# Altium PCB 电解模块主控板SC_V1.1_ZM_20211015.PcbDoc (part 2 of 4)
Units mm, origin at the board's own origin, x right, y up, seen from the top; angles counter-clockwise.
Board outline 150.25 x 100.26 mm, 2 copper layers (Top Layer, Bottom Layer); 222 components, 167 nets, 677 pads, 2045 vias.
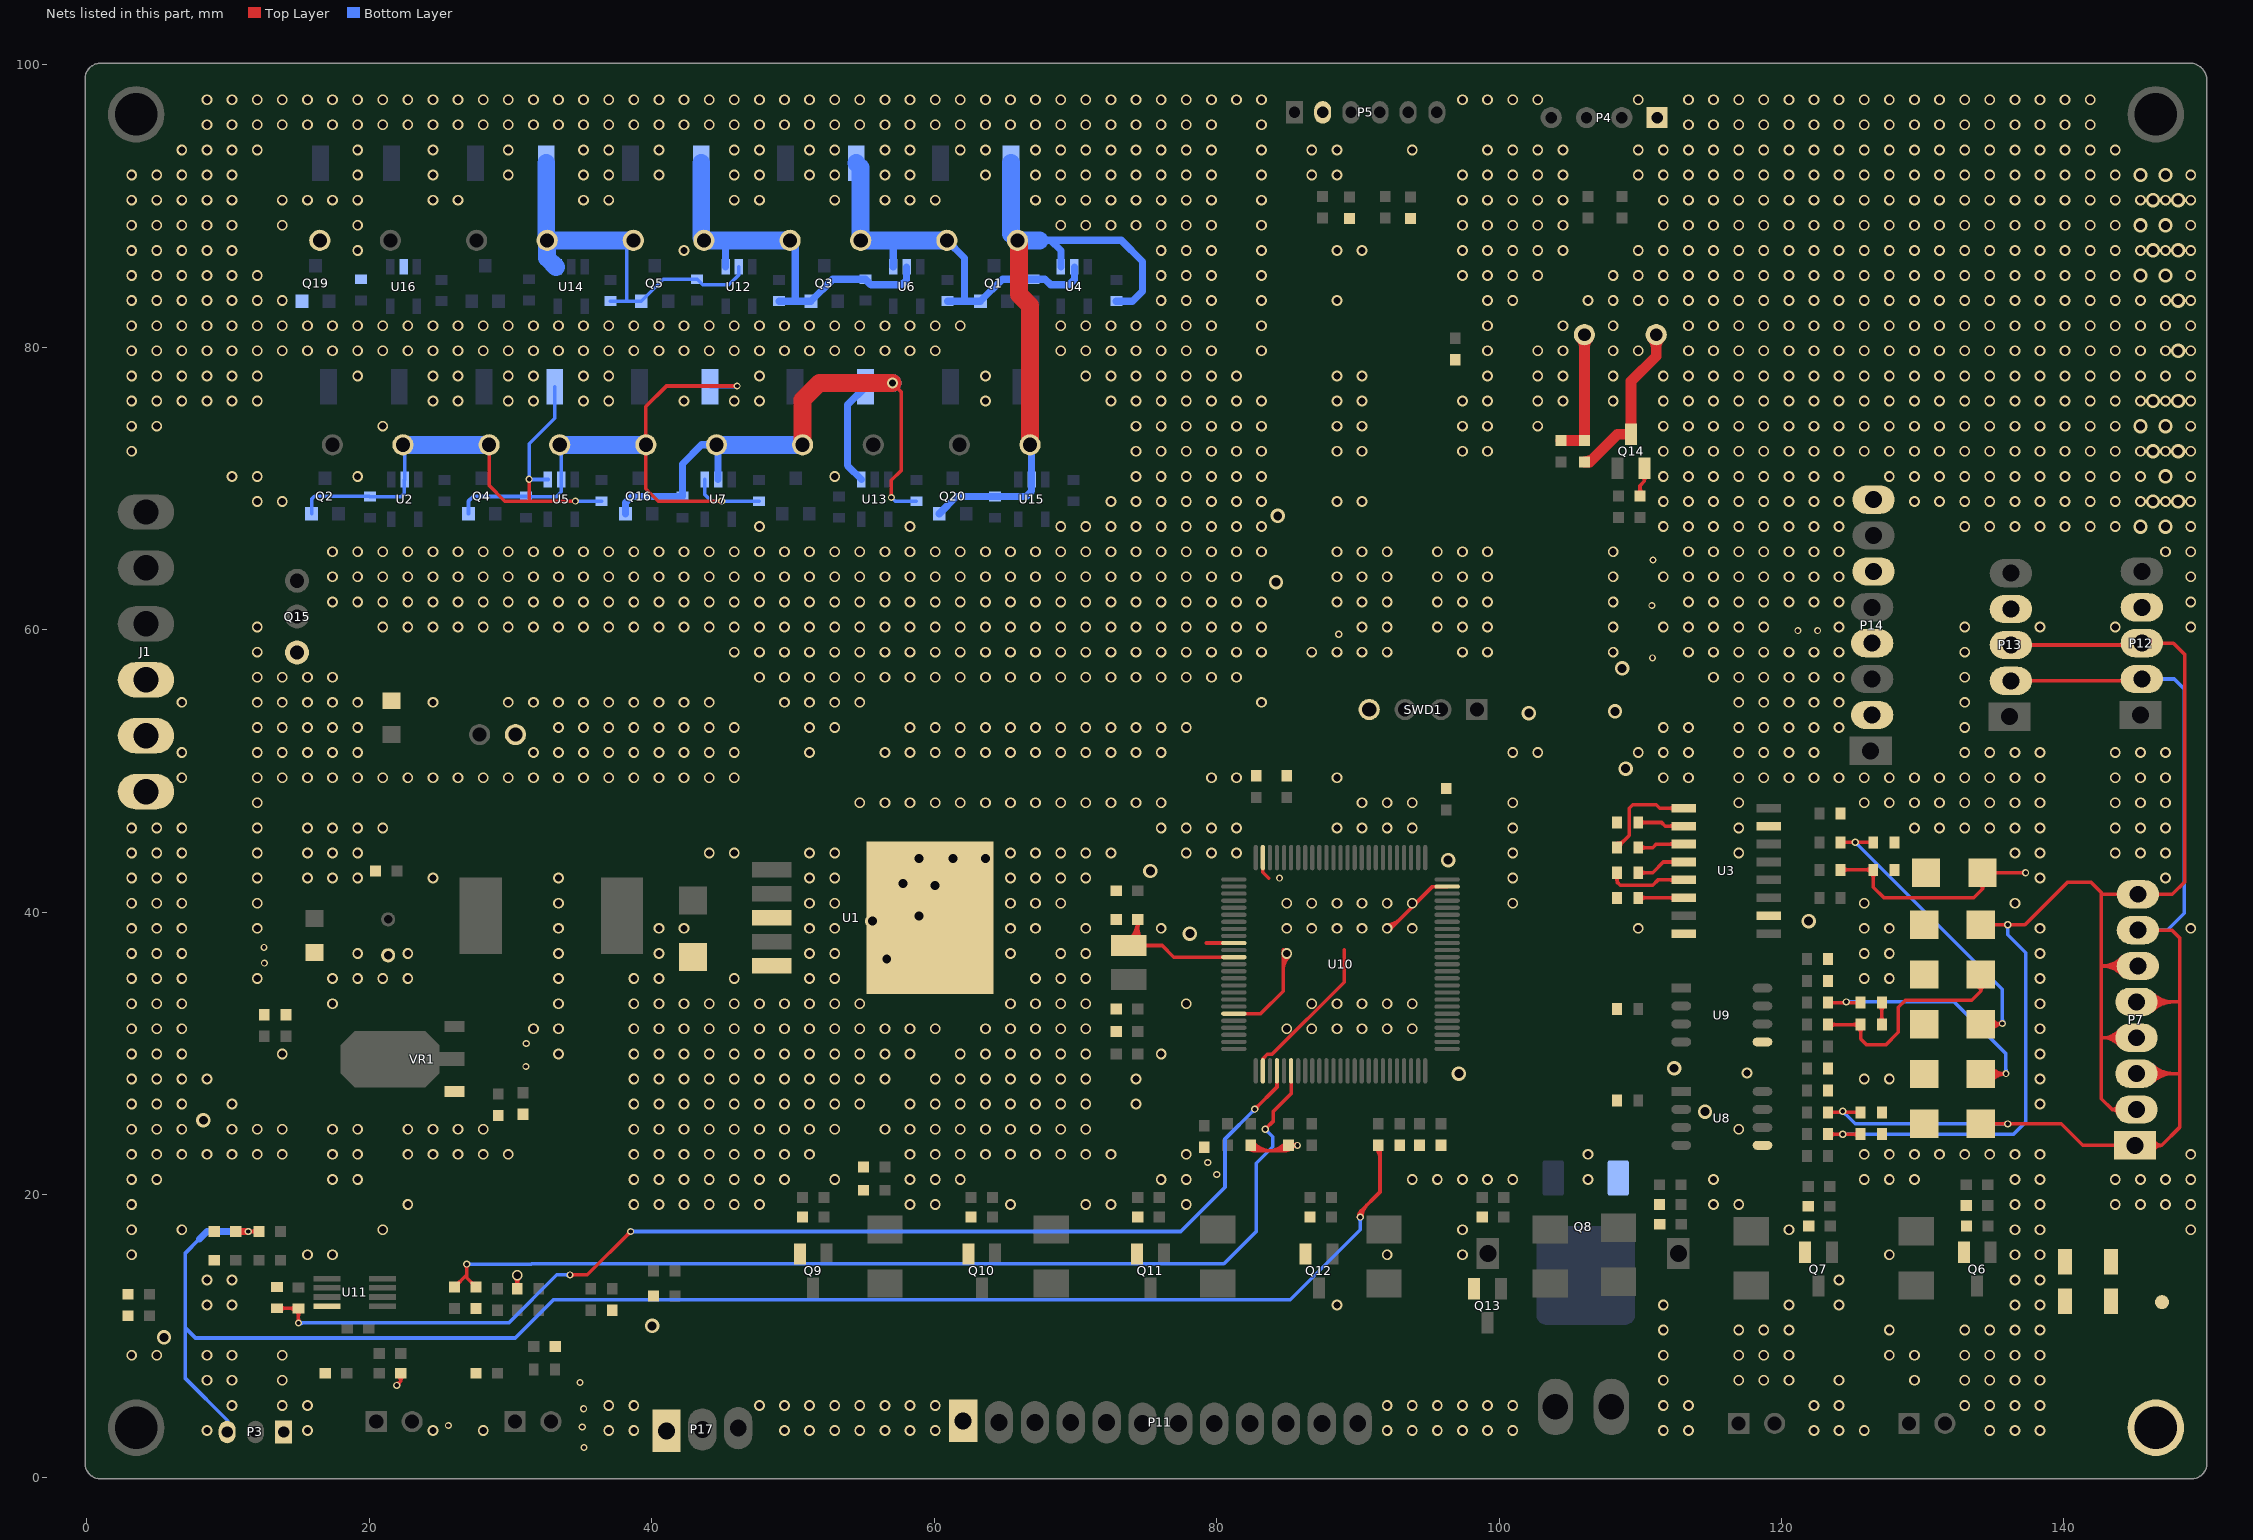
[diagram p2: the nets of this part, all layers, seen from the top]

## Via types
v1: diameter 0.762, hole 0.508, Top Layer to Bottom Layer, tented both sides, 1838 vias
v2: diameter 0.508, hole 0.305, Top Layer to Bottom Layer, tented both sides, 135 vias
v3: diameter 1.016, hole 0.635, Top Layer to Bottom Layer, tented both sides, 63 vias
v4: diameter 2.032, hole 1.524, Top Layer to Bottom Layer, tented both sides, 4 vias
v5: diameter 1.27, hole 0.762, Top Layer to Bottom Layer, tented both sides, 4 vias
v6: diameter 2.54, hole 2.032, Top Layer to Bottom Layer, tented both sides, 1 vias

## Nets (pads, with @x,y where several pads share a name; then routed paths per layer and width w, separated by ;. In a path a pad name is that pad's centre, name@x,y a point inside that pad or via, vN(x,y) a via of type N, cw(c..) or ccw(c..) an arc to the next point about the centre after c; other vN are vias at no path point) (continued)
GND: C1.2 C2.2 C3.1 C4.1 C5.1 C6.1 C8.1 C9.1 C10.1 C12.1 C13.1 C14.1 C15.1 C16.1 C17.1 C22.2 C24.2 C25.2 C27.2 C28.2 C29.2 C30.2 C31.2 C32.1 C33.2 C34.2 C35.2 C36.2 C37.1 C38.1 C39.1 C40.1 C43.2 C45.1 C46.1 C47.1 C50.2 C51.1 C52.1 C55.1 C56.1 C57.1 D3.1 D14.2 D15.2 D16.2 D17.2 D18.2 D19.2 J1.1 J1.2 J1.3 P3.1 P4.1 P5.2 P11.1 P12.4 P13.4 P14.2 P14.4 P14.6 P14.8 P17.1 Q6.2 Q7.2 Q8.2 Q9.2 Q10.2 Q11.2 Q12.2 Q13.2 Q14.2 Q15.1 Q19.2 R22.1 R34.2 R35.2 R36.2 R42.2 R43.2 R44.2 R45.2 R46.2 R59.2 R70.2 R71.2 R72.1 R76.2 R77.2 R79.1 R113.2 SWD1.4 TVS1.1 TVS2.1 TVS3.1 TVS4.1 TVS5.1 TVS6.1 TVS7.1 TVS8.1 TVS9.1 TVS10.1 TVS11.1 TVS12.1 U1.3 U1.5 U1.6 U3.8 U3.10 U3.15 U8.5 U9.5 U10.10 U10.20 U10.27 U10.74 U10.99 U11.4 U16.2 VR1.1 | length 53.5
  Top Layer w0.254: v2(21.946,6.502) 22.225,6.782 ; v2@21.946,6.629 ccw(c21.946,6.936) 22.162,6.719 ccw(c22.379,6.502) v2@22.073,6.502 ; TVS6.1@22.052,7.18 cw(c21.68,6.782) 22.225,6.782 ; TVS6.1@22.225,7.366 22.225,6.782 ; TVS6.1@22.398,7.18 ccw(c22.77,6.782) 22.225,6.782 ; TVS11.1@30.3,13.534 ccw(c29.867,13.967) 30.48,13.967 ccw(c31.093,13.967) TVS11.1@30.66,13.534 ; v1@30.3,14.121 cw(c29.867,13.687) 30.48,13.687 cw(c31.093,13.687) v1@30.66,14.121 ; TVS11.1@30.48,13.335 v1(30.48,14.3) ; 79.272,37.822 U10.10@81.223,37.822 ; U10.20@81.223,32.822 83.114,32.822 84.709,34.417 v1@84.709,37.338 ; C51.1@82.243,23.296 ccw(c82.684,23.737) C51.1@82.684,23.114 ; C51.1@82.423,23.476 ccw(c83.297,24.35) 83.297,23.114 ; C51.1@82.603,23.656 ccw(c83.91,24.963) 83.91,23.114 ; 82.804,23.114 84.709,23.114 C38.1@85.09,23.495 v2(85.725,23.495) ; U10.27@83.273,28.772 83.273,29.629 83.595,29.951 83.926,29.951 89.027,35.052 89.027,37.338 ; U10.99@83.273,43.872 83.273,42.838 83.693,42.418 ; U10.27@83.296,29.522 cw(c83.61,29.522) 83.388,29.744 ; 83.603,23.114 ccw(c83.603,24.963) C38.1@84.91,23.656 ; 84.216,23.114 ccw(c84.216,24.35) C38.1@85.09,23.476 ; 84.709,35.858 cw(c86.189,35.858) v1@85.143,36.904 ; 84.709,36.471 cw(c85.576,36.471) v1(84.963,37.084) ; C38.1@84.829,23.114 ccw(c84.829,23.737) C38.1@85.27,23.296 ; C38.1@85.27,23.315 cw(c85.703,22.882) 85.703,23.495 cw(c85.703,24.108) C38.1@85.27,23.675 ; v2@85.635,23.405 ccw(c85.418,23.188) 85.418,23.495 ccw(c85.418,23.802) v2@85.635,23.585 ; v1(92.075,38.862) ccw(c92.075,39.475) 92.509,39.042 ; v1@92.075,39.116 ccw(c92.075,40.342) 92.942,39.475 ; v1@92.202,38.735 95.289,41.822 U10.74@96.323,41.822 ; R59.2@109.802,69.649 ccw(c109.369,70.082) 109.982,70.082 ccw(c110.595,70.082) R59.2@110.162,69.649 ; R59.2@109.982,69.469 109.982,70.206 110.287,70.51 ; Q14.2@110.108,70.889 cw(c109.797,70.51) 110.287,70.51 ; Q14.2@110.297,71.444 110.287,71.434 110.287,70.51 ; Q14.2@110.473,70.879 ccw(c110.744,70.51) 110.287,70.51 ; C35.2@126.945,32.279 ccw(c126.565,32.66) 127.103,32.66 ccw(c127.641,32.66) C35.2@127.261,32.279 ; C34.2@126.945,33.366 cw(c126.565,32.985) 127.103,32.985 cw(c127.641,32.985) C34.2@127.261,33.366 ; C35.2@127.103,32.046 C34.2@127.103,33.599
  other v1: 8.509,3.302 15.621,3.302 24.511,3.302 28.067,3.302 36.957,3.302 38.735,3.302 49.403,3.302 51.181,3.302 52.959,3.302 54.737,3.302 56.515,3.302 58.293,3.302 60.071,3.302 92.075,3.302 93.853,3.302 95.631,3.302 97.409,3.302 99.187,3.302 100.965,3.302 111.633,3.302 113.411,3.302 122.301,3.302 124.079,3.302 125.857,3.302 134.747,3.302 136.525,3.302 138.303,3.302 10.287,5.08 13.843,5.08 15.621,5.08 36.957,5.08 38.735,5.08 47.625,5.08 49.403,5.08 51.181,5.08 52.959,5.08 54.737,5.08 56.515,5.08 58.293,5.08 60.071,5.08 92.075,5.08 93.853,5.08 95.631,5.08 97.409,5.08 99.187,5.08 100.965,5.08 111.633,5.08 113.411,5.08 122.301,5.08 124.079,5.08 132.969,5.08 134.747,5.08 136.525,5.08 138.303,5.08 8.509,6.858 10.287,6.858 13.843,6.858 111.633,6.858 116.967,6.858 118.745,6.858 120.523,6.858 124.079,6.858 129.413,6.858 132.969,6.858 134.747,6.858 136.525,6.858 138.303,6.858 3.175,8.636 4.953,8.636 8.509,8.636 10.287,8.636 13.843,8.636 111.633,8.636 116.967,8.636 118.745,8.636 120.523,8.636 127.635,8.636 129.413,8.636 132.969,8.636 134.747,8.636 136.525,8.636 138.303,8.636 111.633,10.414 116.967,10.414 118.745,10.414 120.523,10.414 127.635,10.414 132.969,10.414 134.747,10.414 136.525,10.414 138.303,10.414 8.509,12.192 10.287,12.192 88.519,12.192 111.633,12.192 120.523,12.192 124.079,12.192 136.525,12.192 138.303,12.192 8.509,13.97 10.287,13.97 124.079,13.97 136.525,13.97 138.303,13.97 3.175,15.748 15.621,15.748 17.399,15.748 92.075,15.748 97.409,15.748 127.635,15.748 136.525,15.748 138.303,15.748 3.175,17.526 6.731,17.526 20.955,17.526 97.409,17.526 120.523,17.526 136.525,17.526 138.303,17.526 148.971,17.526 3.175,19.304 22.733,19.304 38.735,19.304 40.513,19.304 42.291,19.304 44.069,19.304 45.847,19.304 47.625,19.304 58.293,19.304 60.071,19.304 65.405,19.304 70.739,19.304 72.517,19.304 77.851,19.304 115.189,19.304 116.967,19.304 136.525,19.304 138.303,19.304 143.637,19.304 145.415,19.304 147.193,19.304 148.971,19.304 3.175,21.082 4.953,21.082 17.399,21.082 19.177,21.082 38.735,21.082 40.513,21.082 42.291,21.082 44.069,21.082 45.847,21.082 47.625,21.082 49.403,21.082 52.959,21.082 58.293,21.082 60.071,21.082 61.849,21.082 76.073,21.082 77.851,21.082 93.853,21.082 95.631,21.082 97.409,21.082 99.187,21.082 100.965,21.082 106.299,21.082 115.189,21.082 125.857,21.082 127.635,21.082 129.413,21.082 136.525,21.082 138.303,21.082 143.637,21.082 145.415,21.082 147.193,21.082 148.971,21.082 3.175,22.86 4.953,22.86 6.731,22.86 8.509,22.86 10.287,22.86 12.065,22.86 13.843,22.86 17.399,22.86 19.177,22.86 22.733,22.86 24.511,22.86 26.289,22.86 28.067,22.86 29.845,22.86 38.735,22.86 40.513,22.86 42.291,22.86 44.069,22.86 45.847,22.86 47.625,22.86 49.403,22.86 51.181,22.86 58.293,22.86 60.071,22.86 61.849,22.86 63.627,22.86 65.405,22.86 67.183,22.86 68.961,22.86 70.739,22.86 72.517,22.86 77.851,22.86 106.299,22.86 125.857,22.86 127.635,22.86 129.413,22.86 131.191,22.86 132.969,22.86 134.747,22.86 136.525,22.86 138.303,22.86 148.971,22.86 3.175,24.638 4.953,24.638 6.731,24.638 10.287,24.638 12.065,24.638 13.843,24.638 17.399,24.638 19.177,24.638 22.733,24.638 24.511,24.638 26.289,24.638 28.067,24.638 38.735,24.638 40.513,24.638 42.291,24.638 44.069,24.638 45.847,24.638 47.625,24.638 49.403,24.638 51.181,24.638 52.959,24.638 56.515,24.638 58.293,24.638 60.071,24.638 61.849,24.638 63.627,24.638 65.405,24.638 67.183,24.638 68.961,24.638 70.739,24.638 116.967,24.638 3.175,26.416 4.953,26.416 6.731,26.416 10.287,26.416 38.735,26.416 40.513,26.416 42.291,26.416 44.069,26.416 45.847,26.416 47.625,26.416 49.403,26.416 51.181,26.416 52.959,26.416 54.737,26.416 58.293,26.416 60.071,26.416 61.849,26.416 63.627,26.416 65.405,26.416 67.183,26.416 68.961,26.416 70.739,26.416 74.295,26.416 138.303,26.416 3.175,28.194 4.953,28.194 6.731,28.194 8.509,28.194 38.735,28.194 40.513,28.194 42.291,28.194 44.069,28.194 45.847,28.194 47.625,28.194 49.403,28.194 51.181,28.194 52.959,28.194 54.737,28.194 56.515,28.194 60.071,28.194 61.849,28.194 63.627,28.194 65.405,28.194 67.183,28.194 68.961,28.194 70.739,28.194 74.295,28.194 125.857,28.194 127.635,28.194 138.303,28.194 117.551,28.626 3.175,29.972 4.953,29.972 6.731,29.972 13.843,29.972 33.401,29.972 38.735,29.972 40.513,29.972 42.291,29.972 44.069,29.972 45.847,29.972 47.625,29.972 49.403,29.972 51.181,29.972 52.959,29.972 54.737,29.972 56.515,29.972 58.293,29.972 61.849,29.972 63.627,29.972 65.405,29.972 67.183,29.972 68.961,29.972 70.739,29.972 76.073,29.972 138.303,29.972 3.175,31.75 4.953,31.75 6.731,31.75 31.623,31.75 33.401,31.75 38.735,31.75 40.513,31.75 42.291,31.75 44.069,31.75 45.847,31.75 47.625,31.75 49.403,31.75 51.181,31.75 52.959,31.75 54.737,31.75 56.515,31.75 58.293,31.75 60.071,31.75 63.627,31.75 65.405,31.75 67.183,31.75 68.961,31.75 70.739,31.75 84.963,31.75 86.741,31.75 88.519,31.75 90.297,31.75 92.075,31.75 93.853,31.75 138.303,31.75 3.175,33.528 4.953,33.528 6.731,33.528 17.399,33.528 33.401,33.528 38.735,33.528 40.513,33.528 42.291,33.528 44.069,33.528 45.847,33.528 47.625,33.528 49.403,33.528 51.181,33.528 52.959,33.528 54.737,33.528 65.405,33.528 67.183,33.528 68.961,33.528 70.739,33.528 77.851,33.528 86.741,33.528 88.519,33.528 90.297,33.528 92.075,33.528 93.853,33.528 138.303,33.528 3.175,35.306 4.953,35.306 6.731,35.306 12.065,35.306 17.399,35.306 19.177,35.306 20.955,35.306 22.733,35.306 33.401,35.306 38.735,35.306 40.513,35.306 45.847,35.306 51.181,35.306 52.959,35.306 67.183,35.306 68.961,35.306 70.739,35.306 125.857,35.306 127.635,35.306 138.303,35.306 3.175,37.084 4.953,37.084 6.731,37.084 19.177,37.084 22.733,37.084 33.401,37.084 40.513,37.084 51.181,37.084 52.959,37.084 65.405,37.084 68.961,37.084 70.739,37.084 125.857,37.084 127.635,37.084 138.303,37.084 3.175,38.862 4.953,38.862 6.731,38.862 12.065,38.862 33.401,38.862 40.513,38.862 42.291,38.862 51.181,38.862 52.959,38.862 65.405,38.862 67.183,38.862 70.739,38.862 76.073,38.862 84.963,38.862 86.741,38.862 88.519,38.862 90.297,38.862 93.853,38.862 109.855,38.862 125.857,38.862 127.635,38.862 138.303,38.862 148.971,38.862 3.175,40.64 4.953,40.64 6.731,40.64 12.065,40.64 33.401,40.64 51.181,40.64 52.959,40.64 65.405,40.64 67.183,40.64 68.961,40.64 84.963,40.64 86.741,40.64 88.519,40.64 90.297,40.64 92.075,40.64 93.853,40.64 100.965,40.64 125.857,40.64 136.525,40.64 3.175,42.418 4.953,42.418 6.731,42.418 12.065,42.418 15.621,42.418 17.399,42.418 19.177,42.418 24.511,42.418 33.401,42.418 51.181,42.418 52.959,42.418 65.405,42.418 67.183,42.418 68.961,42.418 70.739,42.418 100.965,42.418 138.303,42.418 147.193,42.418 3.175,44.196 4.953,44.196 6.731,44.196 12.065,44.196 15.621,44.196 17.399,44.196 19.177,44.196 44.069,44.196 45.847,44.196 51.181,44.196 52.959,44.196 65.405,44.196 67.183,44.196 68.961,44.196 70.739,44.196 72.517,44.196 77.851,44.196 79.629,44.196 81.407,44.196 100.965,44.196 116.967,44.196 136.525,44.196 138.303,44.196 143.637,44.196 145.415,44.196 147.193,44.196 3.175,45.974 4.953,45.974 6.731,45.974 12.065,45.974 15.621,45.974 17.399,45.974 19.177,45.974 20.955,45.974 76.073,45.974 77.851,45.974 79.629,45.974 81.407,45.974 88.519,45.974 90.297,45.974 92.075,45.974 93.853,45.974 100.965,45.974 116.967,45.974 129.413,45.974 131.191,45.974 132.969,45.974 134.747,45.974 136.525,45.974 138.303,45.974 143.637,45.974 145.415,45.974 147.193,45.974 12.065,47.752 54.737,47.752 56.515,47.752 58.293,47.752 60.071,47.752 61.849,47.752 63.627,47.752 65.405,47.752 67.183,47.752 68.961,47.752 70.739,47.752 72.517,47.752 74.295,47.752 76.073,47.752 90.297,47.752 92.075,47.752 93.853,47.752 100.965,47.752 116.967,47.752 125.857,47.752 127.635,47.752 129.413,47.752 131.191,47.752 132.969,47.752 134.747,47.752 136.525,47.752 138.303,47.752 143.637,47.752 145.415,47.752 147.193,47.752 6.731,49.53 12.065,49.53 13.843,49.53 15.621,49.53 17.399,49.53 19.177,49.53 20.955,49.53 22.733,49.53 24.511,49.53 26.289,49.53 28.067,49.53 29.845,49.53 31.623,49.53 33.401,49.53 35.179,49.53 36.957,49.53 38.735,49.53 40.513,49.53 42.291,49.53 44.069,49.53 45.847,49.53 79.629,49.53 81.407,49.53 88.519,49.53 111.633,49.53 113.411,49.53 116.967,49.53 118.745,49.53 120.523,49.53 122.301,49.53 124.079,49.53 125.857,49.53 127.635,49.53 129.413,49.53 131.191,49.53 132.969,49.53 134.747,49.53 136.525,49.53 138.303,49.53 143.637,49.53 145.415,49.53 147.193,49.53 6.731,51.308 12.065,51.308 13.843,51.308 15.621,51.308 17.399,51.308 19.177,51.308 31.623,51.308 33.401,51.308 35.179,51.308 36.957,51.308 38.735,51.308 40.513,51.308 42.291,51.308 44.069,51.308 45.847,51.308 51.181,51.308 56.515,51.308 58.293,51.308 60.071,51.308 61.849,51.308 63.627,51.308 65.405,51.308 67.183,51.308 68.961,51.308 70.739,51.308 72.517,51.308 74.295,51.308 76.073,51.308 100.965,51.308 102.743,51.308 109.855,51.308 111.633,51.308 113.411,51.308 116.967,51.308 118.745,51.308 120.523,51.308 122.301,51.308 132.969,51.308 134.747,51.308 136.525,51.308 138.303,51.308 143.637,51.308 145.415,51.308 147.193,51.308 12.065,53.086 13.843,53.086 15.621,53.086 17.399,53.086 19.177,53.086 33.401,53.086 35.179,53.086 36.957,53.086 38.735,53.086 40.513,53.086 42.291,53.086 44.069,53.086 45.847,53.086 51.181,53.086 52.959,53.086 58.293,53.086 60.071,53.086 61.849,53.086 63.627,53.086 65.405,53.086 67.183,53.086 68.961,53.086 70.739,53.086 72.517,53.086 74.295,53.086 76.073,53.086 77.851,53.086 111.633,53.086 113.411,53.086 116.967,53.086 118.745,53.086 120.523,53.086 122.301,53.086 124.079,53.086 132.969,53.086 6.731,54.864 12.065,54.864 13.843,54.864 15.621,54.864 17.399,54.864 19.177,54.864 24.511,54.864 29.845,54.864 31.623,54.864 33.401,54.864 35.179,54.864 36.957,54.864 38.735,54.864 40.513,54.864 42.291,54.864 44.069,54.864 49.403,54.864 51.181,54.864 52.959,54.864 54.737,54.864 83.185,54.864 116.967,54.864 118.745,54.864 120.523,54.864 122.301,54.864 124.079,54.864 132.969,54.864 12.065,56.642 13.843,56.642 15.621,56.642 17.399,56.642 47.625,56.642 49.403,56.642 51.181,56.642 52.959,56.642 54.737,56.642 56.515,56.642 58.293,56.642 60.071,56.642 61.849,56.642 63.627,56.642 65.405,56.642 67.183,56.642 68.961,56.642 70.739,56.642 72.517,56.642 74.295,56.642 76.073,56.642 77.851,56.642 79.629,56.642 81.407,56.642 115.189,56.642 116.967,56.642 118.745,56.642 120.523,56.642 122.301,56.642 124.079,56.642 132.969,56.642 12.065,58.42 45.847,58.42 47.625,58.42 49.403,58.42 51.181,58.42 52.959,58.42 54.737,58.42 56.515,58.42 58.293,58.42 60.071,58.42 61.849,58.42 63.627,58.42 65.405,58.42 67.183,58.42 68.961,58.42 70.739,58.42 72.517,58.42 74.295,58.42 76.073,58.42 77.851,58.42 79.629,58.42 81.407,58.42 83.185,58.42 86.741,58.42 88.519,58.42 90.297,58.42 92.075,58.42 97.409,58.42 99.187,58.42 108.077,58.42 113.411,58.42 115.189,58.42 116.967,58.42 118.745,58.42 120.523,58.42 122.301,58.42 124.079,58.42 132.969,58.42 12.065,60.198 20.955,60.198 22.733,60.198 24.511,60.198 26.289,60.198 28.067,60.198 29.845,60.198 31.623,60.198 33.401,60.198 35.179,60.198 36.957,60.198 38.735,60.198 40.513,60.198 42.291,60.198 44.069,60.198 45.847,60.198 47.625,60.198 49.403,60.198 51.181,60.198 52.959,60.198 54.737,60.198 56.515,60.198 58.293,60.198 60.071,60.198 61.849,60.198 63.627,60.198 65.405,60.198 67.183,60.198 68.961,60.198 70.739,60.198 72.517,60.198 74.295,60.198 76.073,60.198 77.851,60.198 79.629,60.198 81.407,60.198 83.185,60.198 90.297,60.198 92.075,60.198 95.631,60.198 97.409,60.198 99.187,60.198 108.077,60.198 111.633,60.198 113.411,60.198 115.189,60.198 116.967,60.198 118.745,60.198 124.079,60.198 132.969,60.198 138.303,60.198 143.637,60.198 148.971,60.198 17.399,61.976 19.177,61.976 20.955,61.976 22.733,61.976 24.511,61.976 26.289,61.976 28.067,61.976 29.845,61.976 31.623,61.976 33.401,61.976 35.179,61.976 36.957,61.976 38.735,61.976 40.513,61.976 42.291,61.976 44.069,61.976 45.847,61.976 47.625,61.976 49.403,61.976 51.181,61.976 52.959,61.976 54.737,61.976 56.515,61.976 58.293,61.976 60.071,61.976 61.849,61.976 63.627,61.976 65.405,61.976 67.183,61.976 68.961,61.976 70.739,61.976 72.517,61.976 74.295,61.976 76.073,61.976 77.851,61.976 79.629,61.976 81.407,61.976 83.185,61.976 88.519,61.976 90.297,61.976 92.075,61.976 95.631,61.976 97.409,61.976 99.187,61.976 108.077,61.976 113.411,61.976 115.189,61.976 116.967,61.976 118.745,61.976 120.523,61.976 122.301,61.976 124.079,61.976 148.971,61.976 17.399,63.754 19.177,63.754 20.955,63.754 22.733,63.754 24.511,63.754 26.289,63.754 28.067,63.754 29.845,63.754 31.623,63.754 33.401,63.754 35.179,63.754 36.957,63.754 38.735,63.754 40.513,63.754 42.291,63.754 44.069,63.754 45.847,63.754 47.625,63.754 49.403,63.754 51.181,63.754 52.959,63.754 54.737,63.754 56.515,63.754 58.293,63.754 60.071,63.754 61.849,63.754 63.627,63.754 65.405,63.754 67.183,63.754 68.961,63.754 70.739,63.754 72.517,63.754 74.295,63.754 76.073,63.754 77.851,63.754 79.629,63.754 81.407,63.754 88.519,63.754 90.297,63.754 92.075,63.754 95.631,63.754 97.409,63.754 99.187,63.754 108.077,63.754 111.633,63.754 113.411,63.754 115.189,63.754 116.967,63.754 118.745,63.754 120.523,63.754 122.301,63.754 124.079,63.754 148.971,63.754 17.399,65.532 19.177,65.532 20.955,65.532 22.733,65.532 24.511,65.532 26.289,65.532 28.067,65.532 29.845,65.532 31.623,65.532 33.401,65.532 35.179,65.532 36.957,65.532 38.735,65.532 40.513,65.532 42.291,65.532 44.069,65.532 45.847,65.532 47.625,65.532 49.403,65.532 51.181,65.532 52.959,65.532 54.737,65.532 56.515,65.532 58.293,65.532 60.071,65.532 61.849,65.532 63.627,65.532 65.405,65.532 67.183,65.532 68.961,65.532 70.739,65.532 72.517,65.532 74.295,65.532 76.073,65.532 77.851,65.532 79.629,65.532 81.407,65.532 83.185,65.532 88.519,65.532 90.297,65.532 92.075,65.532 95.631,65.532 97.409,65.532 99.187,65.532 108.077,65.532 113.411,65.532 115.189,65.532 116.967,65.532 118.745,65.532 120.523,65.532 122.301,65.532 124.079,65.532 147.193,65.532 148.971,65.532 47.625,67.31 58.293,67.31 68.961,67.31 70.739,67.31 72.517,67.31 74.295,67.31 76.073,67.31 77.851,67.31 79.629,67.31 81.407,67.31 83.185,67.31 111.633,67.31 113.411,67.31 115.189,67.31 116.967,67.31 118.745,67.31 120.523,67.31 122.301,67.31 124.079,67.31 132.969,67.31 134.747,67.31 136.525,67.31 138.303,67.31 140.081,67.31 141.859,67.31 143.637,67.31 148.971,67.31 12.065,69.088 13.843,69.088 72.517,69.088 74.295,69.088 76.073,69.088 77.851,69.088 79.629,69.088 81.407,69.088 83.185,69.088 88.519,69.088 90.297,69.088 111.633,69.088 113.411,69.088 115.189,69.088 116.967,69.088 118.745,69.088 120.523,69.088 122.301,69.088 124.079,69.088 129.413,69.088 131.191,69.088 132.969,69.088 134.747,69.088 136.525,69.088 138.303,69.088 140.081,69.088 141.859,69.088 143.637,69.088 145.415,69.088 147.193,69.088 148.971,69.088 10.287,70.866 12.065,70.866 19.177,70.866 52.959,70.866 74.295,70.866 76.073,70.866 77.851,70.866 79.629,70.866 81.407,70.866 83.185,70.866 111.633,70.866 113.411,70.866 115.189,70.866 116.967,70.866 118.745,70.866 120.523,70.866 122.301,70.866 124.079,70.866 127.635,70.866 129.413,70.866 131.191,70.866 132.969,70.866 134.747,70.866 136.525,70.866 138.303,70.866 140.081,70.866 141.859,70.866 143.637,70.866 145.415,70.866 148.971,70.866 3.175,72.644 74.295,72.644 76.073,72.644 77.851,72.644 79.629,72.644 81.407,72.644 83.185,72.644 88.519,72.644 90.297,72.644 97.409,72.644 99.187,72.644 111.633,72.644 113.411,72.644 115.189,72.644 116.967,72.644 118.745,72.644 120.523,72.644 122.301,72.644 124.079,72.644 125.857,72.644 127.635,72.644 129.413,72.644 131.191,72.644 132.969,72.644 134.747,72.644 136.525,72.644 138.303,72.644 140.081,72.644 141.859,72.644 143.637,72.644 145.415,72.644 147.193,72.644 148.971,72.644 3.175,74.422 4.953,74.422 20.955,74.422 74.295,74.422 76.073,74.422 77.851,74.422 79.629,74.422 81.407,74.422 83.185,74.422 88.519,74.422 90.297,74.422 97.409,74.422 99.187,74.422 102.743,74.422 111.633,74.422 113.411,74.422 115.189,74.422 116.967,74.422 118.745,74.422 120.523,74.422 122.301,74.422 124.079,74.422 125.857,74.422 127.635,74.422 129.413,74.422 131.191,74.422 132.969,74.422 134.747,74.422 136.525,74.422 138.303,74.422 140.081,74.422 141.859,74.422 143.637,74.422 148.971,74.422 3.175,76.2 4.953,76.2 6.731,76.2 8.509,76.2 10.287,76.2 12.065,76.2 24.511,76.2 26.289,76.2 29.845,76.2 31.623,76.2 35.179,76.2 36.957,76.2 42.291,76.2 45.847,76.2 47.625,76.2 63.627,76.2 72.517,76.2 74.295,76.2 76.073,76.2 77.851,76.2 79.629,76.2 81.407,76.2 83.185,76.2 88.519,76.2 90.297,76.2 97.409,76.2 99.187,76.2 102.743,76.2 104.521,76.2 108.077,76.2 111.633,76.2 113.411,76.2 115.189,76.2 116.967,76.2 118.745,76.2 120.523,76.2 122.301,76.2 124.079,76.2 125.857,76.2 127.635,76.2 129.413,76.2 131.191,76.2 132.969,76.2 134.747,76.2 136.525,76.2 138.303,76.2 140.081,76.2 141.859,76.2 143.637,76.2 145.415,76.2 147.193,76.2 148.971,76.2 3.175,77.978 4.953,77.978 6.731,77.978 8.509,77.978 10.287,77.978 12.065,77.978 19.177,77.978 24.511,77.978 26.289,77.978 29.845,77.978 31.623,77.978 35.179,77.978 36.957,77.978 47.625,77.978 63.627,77.978 70.739,77.978 72.517,77.978 74.295,77.978 76.073,77.978 77.851,77.978 79.629,77.978 81.407,77.978 88.519,77.978 90.297,77.978 99.187,77.978 102.743,77.978 104.521,77.978 108.077,77.978 111.633,77.978 113.411,77.978 115.189,77.978 116.967,77.978 118.745,77.978 120.523,77.978 122.301,77.978 124.079,77.978 125.857,77.978 127.635,77.978 129.413,77.978 131.191,77.978 132.969,77.978 134.747,77.978 136.525,77.978 138.303,77.978 140.081,77.978 141.859,77.978 143.637,77.978 145.415,77.978 147.193,77.978 148.971,77.978 3.175,79.756 4.953,79.756 6.731,79.756 8.509,79.756 10.287,79.756 12.065,79.756 13.843,79.756 15.621,79.756 17.399,79.756 19.177,79.756 20.955,79.756 22.733,79.756 24.511,79.756 26.289,79.756 28.067,79.756 29.845,79.756 31.623,79.756 33.401,79.756 35.179,79.756 36.957,79.756 38.735,79.756 40.513,79.756 42.291,79.756 44.069,79.756 45.847,79.756 47.625,79.756 49.403,79.756 51.181,79.756 52.959,79.756 54.737,79.756 56.515,79.756 58.293,79.756 60.071,79.756 68.961,79.756 70.739,79.756 72.517,79.756 74.295,79.756 76.073,79.756 77.851,79.756 79.629,79.756 83.185,79.756 99.187,79.756 102.743,79.756 104.521,79.756 108.077,79.756 109.855,79.756 113.411,79.756 115.189,79.756 116.967,79.756 118.745,79.756 120.523,79.756 122.301,79.756 124.079,79.756 125.857,79.756 127.635,79.756 129.413,79.756 131.191,79.756 132.969,79.756 134.747,79.756 136.525,79.756 138.303,79.756 140.081,79.756 141.859,79.756 143.637,79.756 145.415,79.756 147.193,79.756 148.971,79.756 3.175,81.534 4.953,81.534 6.731,81.534 8.509,81.534 10.287,81.534 12.065,81.534 13.843,81.534 15.621,81.534 17.399,81.534 19.177,81.534 20.955,81.534 22.733,81.534 24.511,81.534 26.289,81.534 28.067,81.534 29.845,81.534 31.623,81.534 33.401,81.534 35.179,81.534 36.957,81.534 38.735,81.534 40.513,81.534 42.291,81.534 44.069,81.534 45.847,81.534 47.625,81.534 49.403,81.534 51.181,81.534 52.959,81.534 54.737,81.534 56.515,81.534 58.293,81.534 60.071,81.534 61.849,81.534 68.961,81.534 70.739,81.534 72.517,81.534 74.295,81.534 76.073,81.534 77.851,81.534 79.629,81.534 83.185,81.534 99.187,81.534 104.521,81.534 108.077,81.534 113.411,81.534 115.189,81.534 116.967,81.534 118.745,81.534 120.523,81.534 122.301,81.534 124.079,81.534 125.857,81.534 127.635,81.534 129.413,81.534 131.191,81.534 132.969,81.534 134.747,81.534 136.525,81.534 138.303,81.534 140.081,81.534 141.859,81.534 143.637,81.534 145.415,81.534 147.193,81.534 148.971,81.534 3.175,83.312 4.953,83.312 6.731,83.312 8.509,83.312 10.287,83.312 12.065,83.312 13.843,83.312 76.073,83.312 77.851,83.312 79.629,83.312 83.185,83.312 88.519,83.312 99.187,83.312 100.965,83.312 106.299,83.312 108.077,83.312 109.855,83.312 111.633,83.312 113.411,83.312 115.189,83.312 116.967,83.312 118.745,83.312 120.523,83.312 122.301,83.312 124.079,83.312 125.857,83.312 127.635,83.312 129.413,83.312 131.191,83.312 132.969,83.312 134.747,83.312 136.525,83.312 138.303,83.312 140.081,83.312 141.859,83.312 143.637,83.312 145.415,83.312 147.193,83.312 148.971,83.312 3.175,85.09 4.953,85.09 6.731,85.09 8.509,85.09 10.287,85.09 12.065,85.09 76.073,85.09 77.851,85.09 79.629,85.09 83.185,85.09 97.409,85.09 99.187,85.09 100.965,85.09 102.743,85.09 108.077,85.09 109.855,85.09 111.633,85.09 113.411,85.09 115.189,85.09 116.967,85.09 118.745,85.09 120.523,85.09 122.301,85.09 124.079,85.09 125.857,85.09 127.635,85.09 129.413,85.09 131.191,85.09 132.969,85.09 134.747,85.09 136.525,85.09 138.303,85.09 140.081,85.09 141.859,85.09 143.637,85.09 148.971,85.09 3.175,86.868 4.953,86.868 6.731,86.868 8.509,86.868 10.287,86.868 19.177,86.868 42.291,86.868 76.073,86.868 77.851,86.868 79.629,86.868 83.185,86.868 88.519,86.868 90.297,86.868 97.409,86.868 99.187,86.868 100.965,86.868 102.743,86.868 104.521,86.868 109.855,86.868 111.633,86.868 113.411,86.868 115.189,86.868 116.967,86.868 118.745,86.868 120.523,86.868 122.301,86.868 124.079,86.868 125.857,86.868 127.635,86.868 129.413,86.868 131.191,86.868 132.969,86.868 134.747,86.868 136.525,86.868 138.303,86.868 140.081,86.868 141.859,86.868 143.637,86.868 145.415,86.868 147.193,86.868 148.971,86.868 3.175,88.646 4.953,88.646 6.731,88.646 8.509,88.646 10.287,88.646 13.843,88.646 19.177,88.646 68.961,88.646 70.739,88.646 72.517,88.646 74.295,88.646 76.073,88.646 77.851,88.646 79.629,88.646 83.185,88.646 97.409,88.646 99.187,88.646 100.965,88.646 102.743,88.646 104.521,88.646 111.633,88.646 113.411,88.646 115.189,88.646 116.967,88.646 118.745,88.646 120.523,88.646 122.301,88.646 124.079,88.646 125.857,88.646 127.635,88.646 129.413,88.646 131.191,88.646 132.969,88.646 134.747,88.646 136.525,88.646 138.303,88.646 140.081,88.646 141.859,88.646 143.637,88.646 148.971,88.646 3.175,90.424 4.953,90.424 6.731,90.424 8.509,90.424 10.287,90.424 13.843,90.424 15.621,90.424 17.399,90.424 19.177,90.424 24.511,90.424 26.289,90.424 35.179,90.424 36.957,90.424 45.847,90.424 47.625,90.424 52.959,90.424 56.515,90.424 58.293,90.424 60.071,90.424 67.183,90.424 68.961,90.424 70.739,90.424 72.517,90.424 74.295,90.424 76.073,90.424 77.851,90.424 79.629,90.424 83.185,90.424 97.409,90.424 99.187,90.424 100.965,90.424 102.743,90.424 104.521,90.424 111.633,90.424 113.411,90.424 115.189,90.424 116.967,90.424 118.745,90.424 120.523,90.424 122.301,90.424 124.079,90.424 125.857,90.424 127.635,90.424 129.413,90.424 131.191,90.424 132.969,90.424 134.747,90.424 136.525,90.424 138.303,90.424 140.081,90.424 141.859,90.424 143.637,90.424 145.415,90.424 147.193,90.424 148.971,90.424 3.175,92.202 4.953,92.202 6.731,92.202 8.509,92.202 10.287,92.202 19.177,92.202 24.511,92.202 29.845,92.202 35.179,92.202 36.957,92.202 40.513,92.202 45.847,92.202 47.625,92.202 51.181,92.202 52.959,92.202 56.515,92.202 58.293,92.202 63.627,92.202 67.183,92.202 68.961,92.202 70.739,92.202 72.517,92.202 74.295,92.202 76.073,92.202 77.851,92.202 79.629,92.202 83.185,92.202 86.741,92.202 88.519,92.202 97.409,92.202 99.187,92.202 100.965,92.202 102.743,92.202 104.521,92.202 109.855,92.202 111.633,92.202 113.411,92.202 115.189,92.202 116.967,92.202 118.745,92.202 120.523,92.202 122.301,92.202 124.079,92.202 125.857,92.202 127.635,92.202 129.413,92.202 131.191,92.202 132.969,92.202 134.747,92.202 136.525,92.202 138.303,92.202 140.081,92.202 141.859,92.202 143.637,92.202 148.971,92.202 6.731,93.98 8.509,93.98 10.287,93.98 12.065,93.98 19.177,93.98 24.511,93.98 29.845,93.98 35.179,93.98 36.957,93.98 40.513,93.98 45.847,93.98 47.625,93.98 51.181,93.98 52.959,93.98 56.515,93.98 58.293,93.98 61.849,93.98 63.627,93.98 67.183,93.98 68.961,93.98 70.739,93.98 72.517,93.98 74.295,93.98 76.073,93.98 77.851,93.98 79.629,93.98 83.185,93.98 86.741,93.98 88.519,93.98 93.853,93.98 99.187,93.98 100.965,93.98 102.743,93.98 104.521,93.98 109.855,93.98 111.633,93.98 113.411,93.98 115.189,93.98 116.967,93.98 118.745,93.98 120.523,93.98 122.301,93.98 124.079,93.98 125.857,93.98 127.635,93.98 129.413,93.98 131.191,93.98 132.969,93.98 134.747,93.98 136.525,93.98 138.303,93.98 140.081,93.98 141.859,93.98 143.637,93.98 8.509,95.758 10.287,95.758 12.065,95.758 13.843,95.758 15.621,95.758 17.399,95.758 19.177,95.758 20.955,95.758 22.733,95.758 24.511,95.758 26.289,95.758 28.067,95.758 29.845,95.758 31.623,95.758 33.401,95.758 35.179,95.758 36.957,95.758 38.735,95.758 40.513,95.758 42.291,95.758 44.069,95.758 45.847,95.758 47.625,95.758 49.403,95.758 51.181,95.758 52.959,95.758 54.737,95.758 56.515,95.758 58.293,95.758 60.071,95.758 61.849,95.758 63.627,95.758 65.405,95.758 67.183,95.758 68.961,95.758 70.739,95.758 72.517,95.758 74.295,95.758 76.073,95.758 77.851,95.758 79.629,95.758 83.185,95.758 113.411,95.758 115.189,95.758 116.967,95.758 118.745,95.758 120.523,95.758 122.301,95.758 124.079,95.758 125.857,95.758 127.635,95.758 129.413,95.758 131.191,95.758 132.969,95.758 134.747,95.758 136.525,95.758 138.303,95.758 140.081,95.758 141.859,95.758 8.509,97.536 10.287,97.536 12.065,97.536 13.843,97.536 15.621,97.536 17.399,97.536 19.177,97.536 20.955,97.536 22.733,97.536 24.511,97.536 26.289,97.536 28.067,97.536 29.845,97.536 31.623,97.536 33.401,97.536 35.179,97.536 36.957,97.536 38.735,97.536 40.513,97.536 42.291,97.536 44.069,97.536 45.847,97.536 47.625,97.536 49.403,97.536 51.181,97.536 52.959,97.536 54.737,97.536 56.515,97.536 58.293,97.536 60.071,97.536 61.849,97.536 63.627,97.536 65.405,97.536 67.183,97.536 68.961,97.536 70.739,97.536 72.517,97.536 74.295,97.536 76.073,97.536 77.851,97.536 79.629,97.536 81.407,97.536 83.185,97.536 97.409,97.536 99.187,97.536 100.965,97.536 102.743,97.536 109.855,97.536 113.411,97.536 115.189,97.536 116.967,97.536 118.745,97.536 120.523,97.536 122.301,97.536 124.079,97.536 125.857,97.536 127.635,97.536 129.413,97.536 131.191,97.536 132.969,97.536 134.747,97.536 136.525,97.536 138.303,97.536 140.081,97.536 141.859,97.536
  other v2: 35.204,2.108 35.077,3.556 25.603,3.658 35.179,4.851 34.925,6.706 80.01,21.438 79.375,22.276 31.09,29.083 31.115,30.709 12.573,36.398 12.548,37.516 84.455,42.418 110.871,58.014 88.646,59.69 121.158,59.944 122.555,59.944 110.82,61.722 110.896,64.948
  other v3: 5.461,9.906 40.03,10.719 8.255,25.273 114.579,25.883 97.155,28.575 112.395,28.956 56.642,36.703 78.105,38.481 55.626,39.37 121.92,39.37 58.928,39.751 60.071,41.91 57.785,42.037 75.311,42.926 96.393,43.688 58.928,43.815 61.341,43.815 63.627,43.815 108.966,50.165 102.108,54.102 108.204,54.229 108.712,57.277 84.201,63.373 145.415,67.31 147.193,67.31 84.328,68.072 146.304,69.088 148.082,69.088 147.193,70.866 146.304,72.644 148.082,72.644 145.415,74.422 147.193,74.422 146.304,76.2 148.082,76.2 148.082,79.756 148.082,83.312 145.415,85.09 147.193,85.09 146.304,86.868 148.082,86.868 145.415,88.646 147.193,88.646 146.304,90.424 148.082,90.424 145.415,92.202 147.193,92.202
J3-2: C28.1 D15.1 R60.2 | length 19.9
  Top Layer w0.254: R60.2@124.182,43.011 C28.1@126.492,43.011 126.492,41.783 127.254,41.021 133.604,41.021 134.239,41.656 ; R60.2@124.34,42.853 cw(c124.72,42.472) 124.72,43.011 cw(c124.72,43.549) R60.2@124.34,43.168 ; C28.1@126.334,42.778 cw(c125.954,42.397) 126.492,42.397 cw(c127.03,42.397) C28.1@126.65,42.778 ; C28.1@126.334,42.853 ccw(c125.954,42.472) 125.954,43.011 ccw(c125.954,43.549) C28.1@126.334,43.168 ; D15.1@134.009,41.957 cw(c133.927,41.656) 134.239,41.656 ; D15.1@134.469,41.957 ccw(c134.551,41.656) 134.239,41.656 ; v2@137.197,42.709 ccw(c136.98,42.492) 136.98,42.799 ccw(c136.98,43.106) v2@137.197,42.889 ; v2(137.287,42.799) D15.1@134.239,42.799 134.239,41.656
J3-3: C27.1 D14.1 R47.2 | length 25.3
  Top Layer w0.254: R47.2@124.182,44.958 C27.1@126.492,44.958 ; D14.1@134.112,32.067 v2@135.572,32.067 ; D14.1@134.657,31.774 cw(c135.148,31.511) 135.148,32.067 cw(c135.148,32.624) D14.1@134.657,32.361 ; D14.1@134.881,31.654 cw(c135.572,31.282) v2@135.572,32.067 ; D14.1@134.881,32.481 ccw(c135.572,32.853) v2@135.572,32.067 ; 135.176,32.067 ccw(c135.176,32.591) v2@135.546,32.221 ; v2(135.636,32.131) v2@135.572,32.067
  Bottom Layer w0.254: v2@125.222,44.831 cw(c125.222,44.524) 125.439,44.741 cw(c125.656,44.958) v2@125.349,44.958 ; v2(125.222,44.958) 135.636,34.544 v2(135.636,32.131) ; v2@135.546,32.221 ccw(c135.329,32.438) 135.636,32.438 ccw(c135.943,32.438) v2@135.726,32.221
J3-4: C31.1 D17.1 P7.2 P7.4 P7.6 P7.8 P12.3 P13.3 R69.2 | length 113.4
  Top Layer w0.254: R69.2@123.293,24.285 v2(124.333,24.285) C31.1@125.603,24.285 ; R69.2@123.451,24.128 cw(c123.831,23.747) 123.831,24.285 cw(c123.831,24.824) R69.2@123.451,24.443 ; v2@124.243,24.195 ccw(c124.026,23.979) 124.026,24.285 ccw(c124.026,24.592) v2@124.243,24.375 ; v2@124.423,24.195 cw(c124.64,23.979) 124.64,24.285 cw(c124.64,24.592) v2@124.423,24.375 ; C31.1@125.445,24.128 ccw(c125.065,23.747) 125.065,24.285 ccw(c125.065,24.824) C31.1@125.445,24.443 ; D17.1@134.112,39.116 v2(136.017,39.116) 137.236,39.116 140.233,42.113 141.935,42.113 142.646,41.402 142.646,31.013 ; v2@135.927,39.026 ccw(c135.71,38.809) 135.71,39.116 ccw(c135.71,39.423) v2@135.927,39.206 ; v2@136.107,39.026 cw(c136.324,38.809) 136.324,39.116 cw(c136.324,39.423) v2@136.107,39.206 ; P13.3@136.244,58.928 145.388,58.928 P12.3@145.515,59.055 147.752,59.055 148.565,58.242 148.565,42.164 147.676,41.275 P7.8@145.234,41.275 142.773,41.275 ; P7.2@143.809,25.75 ccw(c143.408,25.611) 143.408,26.035 ; P7.2@143.809,26.32 cw(c143.408,26.459) 143.408,26.035 ; P7.4@143.968,30.55 ccw(c142.748,29.515) 142.748,31.115 ; P7.4@143.968,31.68 cw(c142.748,32.715) 142.748,31.115 ; P7.6@144.102,35.593 ccw(c142.697,34.256) 142.697,36.195 ; P7.6@144.102,36.797 cw(c142.697,38.134) 142.697,36.195 ; P7.4@144.162,30.714 ccw(c143.297,29.98) 143.297,31.115 ccw(c143.297,32.25) P7.4@144.162,31.516 ; P7.6@144.286,35.768 ccw(c143.29,34.82) 143.29,36.195 ccw(c143.29,37.57) P7.6@144.286,36.622 ; P7.2@145.134,26.035 143.408,26.035 ; P7.4@145.134,31.115 142.748,31.115 ; P7.6@145.234,36.195 142.697,36.195 ; 142.646,31.013 142.748,31.115 ; 142.646,31.013 142.646,26.797 143.408,26.035
  Bottom Layer w0.254: v2(124.333,24.285) 136.426,24.285 137.287,25.146 137.287,37.135 136.017,38.405 v2(136.017,39.116) ; v2@124.423,24.195 cw(c124.64,23.979) 124.64,24.285 cw(c124.64,24.592) v2@124.423,24.375 ; v2@135.927,39.026 cw(c135.71,38.809) 136.017,38.809 cw(c136.324,38.809) v2@136.107,39.026
J3-7: C35.1 D19.1 R75.2 | length 19.2
  Top Layer w0.254: R75.2@123.293,32.046 C35.1@125.603,32.046 125.603,31.03 126.026,30.607 127.381,30.607 128.27,31.496 128.27,33.274 128.778,33.782 133.477,33.782 134.112,34.417 ; R75.2@123.451,31.889 cw(c123.831,31.508) 123.831,32.046 cw(c123.831,32.585) R75.2@123.451,32.204 ; C35.1@125.445,31.814 cw(c125.065,31.433) 125.603,31.433 cw(c126.141,31.433) C35.1@125.761,31.814 ; C35.1@125.445,31.889 ccw(c125.065,31.508) 125.065,32.046 ccw(c125.065,32.585) C35.1@125.445,32.204 ; D19.1@133.86,34.756 cw(c133.758,34.417) 134.112,34.417 ; D19.1@134.112,35.592 134.112,34.417 ; D19.1@134.364,34.756 ccw(c134.466,34.417) 134.112,34.417
J3-8: C34.1 D18.1 R74.2 | length 23.8
  Top Layer w0.254: R74.2@123.293,33.599 C34.1@125.603,33.599 ; D18.1@134.112,28.543 v2@135.858,28.543 ; D18.1@134.607,28.172 cw(c135.35,27.615) 135.35,28.543 cw(c135.35,29.472) D18.1@134.607,28.915 ; D18.1@134.81,28.019 cw(c135.858,27.233) v2@135.858,28.543 ; D18.1@134.81,29.067 ccw(c135.858,29.853) v2@135.858,28.543 ; 135.507,28.543 ccw(c135.507,28.958) v2@135.8,28.665 ; v2(135.89,28.575) v2@135.858,28.543
  Bottom Layer w0.254: v2(124.587,33.655) 132.207,33.655 135.89,29.972 v2(135.89,28.575) ; v2@124.677,33.565 cw(c124.894,33.348) 124.894,33.655 cw(c124.894,33.962) v2@124.677,33.745 ; v2@135.8,28.665 ccw(c135.583,28.882) 135.89,28.882 ccw(c136.197,28.882) v2@135.98,28.665
J3-9: C30.1 D16.1 P7.1 P7.3 P7.5 P7.7 P12.2 P13.2 R62.2 | length 99.3
  Top Layer w0.254: R62.2@123.293,25.837 C30.1@125.603,25.837 ; D16.1@134.112,25.019 v2(136.017,25.019) 139.802,25.019 141.326,23.495 P7.1@145.034,23.495 146.914,23.495 ; v2@135.927,24.929 ccw(c135.71,24.712) 135.71,25.019 ccw(c135.71,25.326) v2@135.927,25.109 ; v2@136.107,24.929 cw(c136.324,24.712) 136.324,25.019 cw(c136.324,25.326) v2@136.107,25.109 ; P13.2@136.244,56.388 145.388,56.388 P12.2@145.515,56.515 ; P7.3@145.134,28.575 148.158,28.575 148.184,28.6 ; P7.5@145.134,33.655 148.158,33.655 148.184,33.63 ; P7.7@145.234,38.735 147.65,38.735 148.184,38.202 148.184,33.63 ; P7.3@146.072,28.137 cw(c147.128,27.081) 147.128,28.575 cw(c147.128,30.069) P7.3@146.072,29.013 ; P7.5@146.072,33.217 cw(c147.128,32.161) 147.128,33.655 cw(c147.128,35.149) P7.5@146.072,34.093 ; P7.3@146.251,27.958 cw(c147.742,26.467) 147.742,28.575 cw(c147.742,30.683) P7.3@146.251,29.192 ; P7.5@146.251,33.038 cw(c147.742,31.547) 147.742,33.655 cw(c147.742,35.763) P7.5@146.251,34.272 ; P7.1@146.323,23.121 cw(c146.914,22.841) 146.914,23.495 ; P7.1@146.323,23.869 ccw(c146.914,24.149) 146.914,23.495 ; 146.914,23.495 148.184,24.765 148.184,28.6 ; 148.184,28.6 148.184,33.63
  Bottom Layer w0.254: v2@124.333,25.781 cw(c124.333,25.474) 124.55,25.691 cw(c124.767,25.908) v2@124.46,25.908 ; v2(124.333,25.908) 125.222,25.019 v2(136.017,25.019) ; v2@135.927,24.929 ccw(c135.71,24.712) 135.71,25.019 ccw(c135.71,25.326) v2@135.927,25.109 ; P7.7@145.234,38.735 147.32,38.735 148.514,39.929 148.514,55.804 147.803,56.515 P12.2@145.515,56.515
LOW: P3.3 R5.2 R7.1 TVS1.2 | length 118
  Top Layer w0.254: v2@11.52,17.309 cw(c11.737,17.092) 11.737,17.399 cw(c11.737,17.706) v2@11.52,17.489 ; R5.2@11.965,17.253 ccw(c11.684,17.055) 11.684,17.399 ; R5.2@11.965,17.545 cw(c11.684,17.743) 11.684,17.399 ; R5.2@12.192,17.399 11.684,17.399 ; v2@90.043,18.415 cw(c90.656,18.415) 90.223,18.849 ; v2@90.08,18.505 ccw(c89.863,18.722) 90.17,18.722 ccw(c90.477,18.722) v2@90.26,18.505 ; v2(90.17,18.415) 90.17,18.796 91.567,20.193 91.567,23.368 R7.1@91.44,23.495 ; v2@90.297,18.415 cw(c91.523,18.415) 90.656,19.282 ; R7.1@91.26,23.296 cw(c90.52,22.556) 91.567,22.556
  Top Layer w0.508: TVS1.2@10.541,17.399 v2(11.43,17.399)
  Bottom Layer w0.254: 7.97,16.86 6.985,15.875 6.985,10.566 ; P3.3@9.97,3.2 9.97,4 6.985,6.985 6.985,10.566 ; v2@90.08,18.325 cw(c89.863,18.108) 90.17,18.108 cw(c90.477,18.108) v2@90.26,18.325 ; v2(90.17,18.415) 90.17,17.526 85.217,12.573 33.045,12.573 30.328,9.855 7.696,9.855 6.985,10.566
  Bottom Layer w0.508: 7.97,16.86 8.509,17.399 v2(11.43,17.399)
NetBEEP1_1: BEEP1.1 R56.1 R58.2 | length 10.4
  Top Layer w0.762: R56.1@104.394,73.406 R58.2@106.045,73.406 BEEP1.1@106.045,80.772 ; BEEP1.1@105.784,80.638 cw(c105.154,80.008) 106.045,80.008 cw(c106.936,80.008) BEEP1.1@106.306,80.638
NetBEEP1_2: BEEP1.2 Q14.3 R58.1 | length 13.9
  Top Layer w0.762: R58.1@106.045,71.882 106.426,71.882 108.388,73.844 Q14.3@109.347,73.844 109.347,77.597 111.125,79.375 BEEP1.2@111.125,80.772 ; R58.1@106.045,71.901 ccw(c106.045,72.867) 106.728,72.184 ; BEEP1.2@110.864,80.638 cw(c110.234,80.008) 111.125,80.008 cw(c112.016,80.008) BEEP1.2@111.386,80.638
NetC6_2: C6.2 R24.1 U10.29 | length 88.3
  Top Layer w0.254: C6.2@13.462,11.962 14.962,11.962 R24.1@14.986,11.938 v2(14.986,10.922) ; C6.2@13.695,11.804 cw(c14.075,11.424) 14.075,11.962 cw(c14.075,12.5) C6.2@13.695,12.12 ; 14.315,11.962 cw(c14.315,11.342) R24.1@14.753,11.78 ; 14.431,11.962 ccw(c14.431,12.418) R24.1@14.753,12.096 ; R24.1@14.828,11.78 cw(c14.448,11.4) 14.986,11.4 cw(c15.524,11.4) R24.1@15.144,11.78 ; v2@14.896,11.012 ccw(c14.679,11.229) 14.986,11.229 ccw(c15.293,11.229) v2@15.076,11.012 ; v2(34.214,14.326) 35.433,14.326 v2(38.506,17.399) ; v2@34.304,14.236 cw(c34.52,14.019) 34.52,14.326 cw(c34.52,14.632) v2@34.304,14.415 ; v2@38.379,17.399 cw(c38.073,17.399) 38.29,17.182 cw(c38.506,16.965) v2@38.506,17.272 ; v2(82.702,26.06) 84.273,27.631 U10.29@84.273,28.772 ; v2@82.702,26.187 ccw(c82.702,26.494) 82.919,26.277 ccw(c83.136,26.06) v2@82.829,26.06
  Bottom Layer w0.254: v2(14.986,10.922) 29.883,10.922 33.287,14.326 v2(34.214,14.326) ; v2@15.076,10.832 cw(c15.293,10.615) 15.293,10.922 cw(c15.293,11.229) v2@15.076,11.012 ; v2@34.124,14.236 ccw(c33.907,14.019) 33.907,14.326 ccw(c33.907,14.632) v2@34.124,14.415 ; v2(38.506,17.399) 77.47,17.399 80.594,20.523 80.594,23.952 v2(82.702,26.06) ; v2@38.596,17.309 cw(c38.813,17.092) 38.813,17.399 cw(c38.813,17.706) v2@38.596,17.489 ; v2@82.575,26.06 cw(c82.269,26.06) 82.486,25.844 cw(c82.702,25.627) v2@82.702,25.933
NetC7_1: C7.1 C44.2 Q20.2 R1.1 R27.1 R114.2 U4.1 U15.2 | length 46.9
  Top Layer w1.27: C7.1@65.898,87.579 66.015,87.463 66.015,83.744 66.787,82.971 C44.2@66.787,73.101
  Bottom Layer w0.508: Q20.2@60.366,68.219 61.583,69.437 R114.2@64.313,69.437 66.516,69.437 66.904,69.825 U15.2@66.904,70.644 66.904,72.985 C44.2@66.787,73.101 ; 67.462,87.579 68.25,87.579 ; U4.1@68.976,85.7 68.976,86.853 68.25,87.579 ; R27.1@72.898,83.272 74.051,83.272 74.752,83.972 74.752,86.081 73.254,87.579 68.25,87.579
  Bottom Layer w1.27: R1.1@65.456,93.04 65.456,88.022 C7.1@65.898,87.579 67.462,87.579
NetC7_2: C7.2 C18.1 Q1.2 R28.2 R30.1 R65.1 U4.2 U6.1 | length 29.2
  Bottom Layer w0.508: U6.1@57.102,85.7 57.102,87.556 57.125,87.579 ; C7.2@60.898,87.579 62.154,86.324 62.154,83.272 ; R65.1@60.954,83.272 62.154,83.272 ; U4.2@69.926,85.7 69.926,84.785 69.571,84.43 68.25,84.43 67.857,84.822 R28.2@67.031,84.822 64.834,84.822 Q1.2@63.287,83.275 63.284,83.272 62.154,83.272
  Bottom Layer w1.27: R30.1@54.482,93.04 54.799,92.724 C18.1@54.799,87.579 57.125,87.579 C7.2@60.898,87.579
NetC11_2: C11.2 C19.1 Q2.2 R29.2 R53.1 R64.1 U2.2 U5.1 | length 39
  Top Layer w0.254: C19.1@28.488,73.101 28.488,70.216 29.591,69.113 31.217,69.113 ; v2(31.318,70.663) 31.318,69.215 31.217,69.113 ; v2(34.595,69.113) 31.217,69.113
  Bottom Layer w0.254: Q2.2@15.916,68.219 15.916,69.256 16.129,69.469 20.008,69.469 R29.2@20.041,69.437 22.269,69.437 22.479,69.647 22.479,70.619 U2.2@22.504,70.644 22.504,72.985 C11.2@22.388,73.101 ; U5.1@32.654,70.644 31.337,70.644 v2(31.318,70.663) 31.318,73.177 33.133,74.993 R53.1@33.133,77.216 ; v2(34.595,69.113) 34.603,69.105 R64.1@36.462,69.105
  Bottom Layer w1.27: C11.2@22.388,73.101 C19.1@28.488,73.101
NetC12_2: C12.2 R18.1 U10.31 | length 74.7
  Top Layer w0.254: R18.1@26.035,13.462 26.899,14.326 ; v2@26.809,14.998 cw(c26.592,14.781) 26.899,14.781 cw(c27.205,14.781) v2@26.988,14.998 ; v2(26.899,15.088) 26.899,14.326 ; C12.2@27.559,13.462 26.899,14.122 26.899,14.326 ; v2(83.439,24.638) 84.023,25.222 84.023,25.908 85.273,27.158 U10.31@85.273,28.772 ; v2@83.439,24.765 ccw(c83.439,25.072) 83.656,24.855 ccw(c83.873,24.638) v2@83.566,24.638
  Bottom Layer w0.254: v2(26.899,15.088) 31.471,15.088 31.496,15.113 80.518,15.113 82.804,17.399 82.804,22.225 83.972,23.393 83.972,24.105 v2(83.439,24.638) ; v2@26.988,14.998 cw(c27.205,14.781) 27.205,15.088 cw(c27.205,15.394) v2@26.988,15.177 ; v2@83.439,24.511 cw(c83.439,24.204) 83.656,24.421 cw(c83.873,24.638) v2@83.566,24.638
NetC18_2: C18.2 C20.1 Q3.2 R66.2 R68.1 R88.1 U6.2 U12.1 | length 29
  Bottom Layer w0.508: 44.983,87.579 45.227,87.335 U12.1@45.227,85.7 ; R88.1@49.009,83.272 50.165,83.272 ; C18.2@49.799,87.579 50.165,87.213 50.165,83.272 ; U6.2@58.052,85.7 58.052,84.773 57.709,84.43 55.517,84.43 R66.2@55.124,84.822 52.824,84.822 Q3.2@51.276,83.275 51.273,83.272 50.165,83.272
  Bottom Layer w1.27: R68.1@43.508,93.04 43.508,87.77 C20.1@43.699,87.579 44.983,87.579 C18.2@49.799,87.579
NetC19_2: C19.2 C21.1 Q4.2 R67.2 R83.1 R87.1 U5.2 U7.1 | length 42.9
  Top Layer w0.254: v2(44.958,69.113) 40.462,69.113 39.588,69.988 C21.1@39.588,73.101 39.588,75.808 41.046,77.267 v2(46.05,77.267)
  Bottom Layer w0.254: Q4.2@27.028,68.219 27.028,69.116 27.356,69.444 31.102,69.444 R67.2@31.109,69.437 33.267,69.437 33.604,69.774 U5.2@33.604,70.644 33.604,72.985 C19.2@33.488,73.101 ; U7.1@43.754,70.644 43.754,69.581 44.23,69.105 R87.1@47.6,69.105 ; R83.1@44.143,77.216 45.999,77.216 v2(46.05,77.267)
  Bottom Layer w1.27: C19.2@33.488,73.101 C21.1@39.588,73.101
NetC20_2: C20.2 C41.1 Q5.2 R89.2 R91.1 R100.1 U12.2 U14.1 | length 29
  Bottom Layer w0.254: R100.1@37.065,83.272 38.227,83.272 ; C20.2@38.699,87.579 38.227,87.107 38.227,83.272 ; U12.2@46.177,85.7 46.177,85.141 45.466,84.43 43.611,84.43 R89.2@43.218,84.822 40.814,84.822 Q5.2@39.266,83.275 39.263,83.272 38.227,83.272
  Bottom Layer w1.27: R91.1@32.535,93.04 32.535,87.644 C41.1@32.599,87.579 ; U14.1@33.215,85.7 32.599,86.316 C41.1@32.599,87.579 ; C20.2@38.699,87.579 C41.1@32.599,87.579
NetC21_2: C21.2 C42.1 Q16.2 R90.2 R95.1 R99.1 U7.2 U13.1 | length 48.8
  Top Layer w0.254: v2(56.972,69.367) 56.972,70.587 57.658,71.272 57.658,76.86 v1(57.048,77.47)
  Top Layer w1.27: C42.1@50.688,73.101 50.688,76.291 51.867,77.47 v1(57.048,77.47)
  Bottom Layer w0.254: v2(56.972,69.367) 57.235,69.105 R99.1@58.737,69.105
  Bottom Layer w0.508: Q16.2@38.141,68.219 38.141,69.002 38.583,69.444 42.17,69.444 R90.2@42.177,69.437 42.177,71.742 43.536,73.101 C21.2@44.588,73.101 44.704,72.985 U7.2@44.704,70.644 ; U13.1@54.854,70.644 53.873,71.624 53.873,75.936 R95.1@55.153,77.216 ; R95.1@55.407,77.216 R95.1@55.407,77.47
  Bottom Layer w1.27: C21.2@44.588,73.101 C42.1@50.688,73.101 ; R95.1@55.407,77.47 v1(57.048,77.47)
NetC23_1: C23.1 U3.1 | length 8.7
  Top Layer w0.254: C23.1@108.355,44.577 109.22,45.442 109.22,47.371 109.474,47.625 111.125,47.625 111.379,47.371 U3.1@113.068,47.371 ; C23.1@108.355,44.875 ccw(c108.355,45.594) 108.864,45.086 ; C23.1@108.578,44.652 cw(c108.935,44.652) C23.1@108.683,44.905 ; U3.1@112.384,47.245 ccw(c112.08,46.942) 112.08,47.371 ccw(c112.08,47.8) U3.1@112.384,47.497
NetC23_2: C23.2 U3.3 | length 4.8
  Top Layer w0.254: C23.2@109.855,44.577 110.871,44.577 111.125,44.831 U3.3@113.068,44.831 ; C23.2@110.013,44.419 cw(c110.393,44.039) 110.393,44.577 cw(c110.393,45.115) C23.2@110.013,44.735 ; U3.3@112.384,44.705 ccw(c112.08,44.402) 112.08,44.831 ccw(c112.08,45.26) U3.3@112.384,44.957
NetC24_1: C24.1 U3.6 | length 4.7
  Top Layer w0.254: C24.1@109.855,41.021 U3.6@113.068,41.021 ; C24.1@110.013,40.863 cw(c110.393,40.483) 110.393,41.021 cw(c110.393,41.559) C24.1@110.013,41.179 ; U3.6@112.384,40.895 ccw(c112.08,40.592) 112.08,41.021 ccw(c112.08,41.45) U3.6@112.384,41.147
NetC25_1: C25.1 U3.2 | length 4.8
  Top Layer w0.254: C25.1@109.855,46.355 111.506,46.355 111.76,46.101 U3.2@113.068,46.101 ; C25.1@110.013,46.197 cw(c110.393,45.817) 110.393,46.355 cw(c110.393,46.893) C25.1@110.013,46.513 ; U3.2@112.384,45.975 ccw(c112.08,45.672) 112.08,46.101 ccw(c112.08,46.53) U3.2@112.384,46.227
NetC26_1: C26.1 U3.5 | length 7.1
  Top Layer w0.254: C26.1@108.197,42.566 cw(c107.817,42.186) 108.355,42.186 cw(c108.893,42.186) C26.1@108.513,42.566 ; C26.1@108.355,42.799 108.355,42.14 108.585,41.91 110.871,41.91 111.252,42.291 U3.5@113.068,42.291 ; U3.5@112.384,42.165 ccw(c112.08,41.862) 112.08,42.291 ccw(c112.08,42.72) U3.5@112.384,42.417
NetC26_2: C26.2 U3.4 | length 5
  Top Layer w0.254: C26.2@109.855,42.799 110.871,42.799 111.633,43.561 U3.4@113.068,43.561 ; C26.2@110.013,42.641 cw(c110.393,42.261) 110.393,42.799 cw(c110.393,43.337) C26.2@110.013,42.957 ; U3.4@112.384,43.435 ccw(c112.08,43.132) 112.08,43.561 ccw(c112.08,43.99) U3.4@112.384,43.687
NetC32_2: C32.2 pad.0@146.5,3.5 R72.2 TP4.1
NetC36_1: C36.1 U10.12 Y1.2 | length 13.3
  Top Layer w0.254: Y1.2@73.846,38.09 ccw(c72.457,39.479) C36.1@74.422,39.479 ; Y1.2@74.026,37.91 ccw(c73.07,38.866) 74.422,38.866 ; C36.1@74.242,39.317 cw(c73.809,38.884) 74.422,38.884 cw(c75.035,38.884) C36.1@74.602,39.317 ; 74.422,38.827 ccw(c75.465,38.827) Y1.2@74.728,38.09 ; C36.1@74.422,39.497 74.422,37.776 74.549,37.649 76.143,37.649 76.97,36.822 U10.12@81.223,36.822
